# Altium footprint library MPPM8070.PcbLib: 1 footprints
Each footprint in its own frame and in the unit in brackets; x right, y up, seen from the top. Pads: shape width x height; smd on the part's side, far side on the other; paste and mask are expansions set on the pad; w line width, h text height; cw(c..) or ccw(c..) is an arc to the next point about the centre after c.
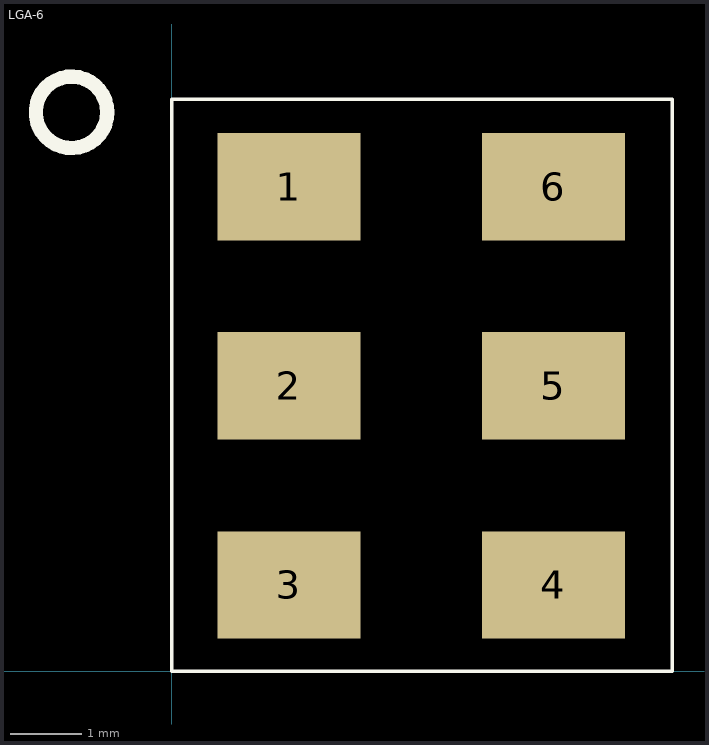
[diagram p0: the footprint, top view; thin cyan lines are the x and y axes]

## LGA-6 [mm]
pads (6):
  rect 2x1.5 smd: 1(1.64,6.78) 2(1.64,3.995) 3(1.64,1.21) 4(5.34,1.21) 5(5.34,3.995) 6(5.34,6.78)
Top Overlay:
  circle w0.2: c-1.401,7.82 r0.5
  lines w0.05: 0,0 0,8 7,8 7,0 0,0
3D body: height 4.32, standoff 0, extent 0,0 7,8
